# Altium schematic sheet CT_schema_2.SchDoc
size 349 x 342 mm
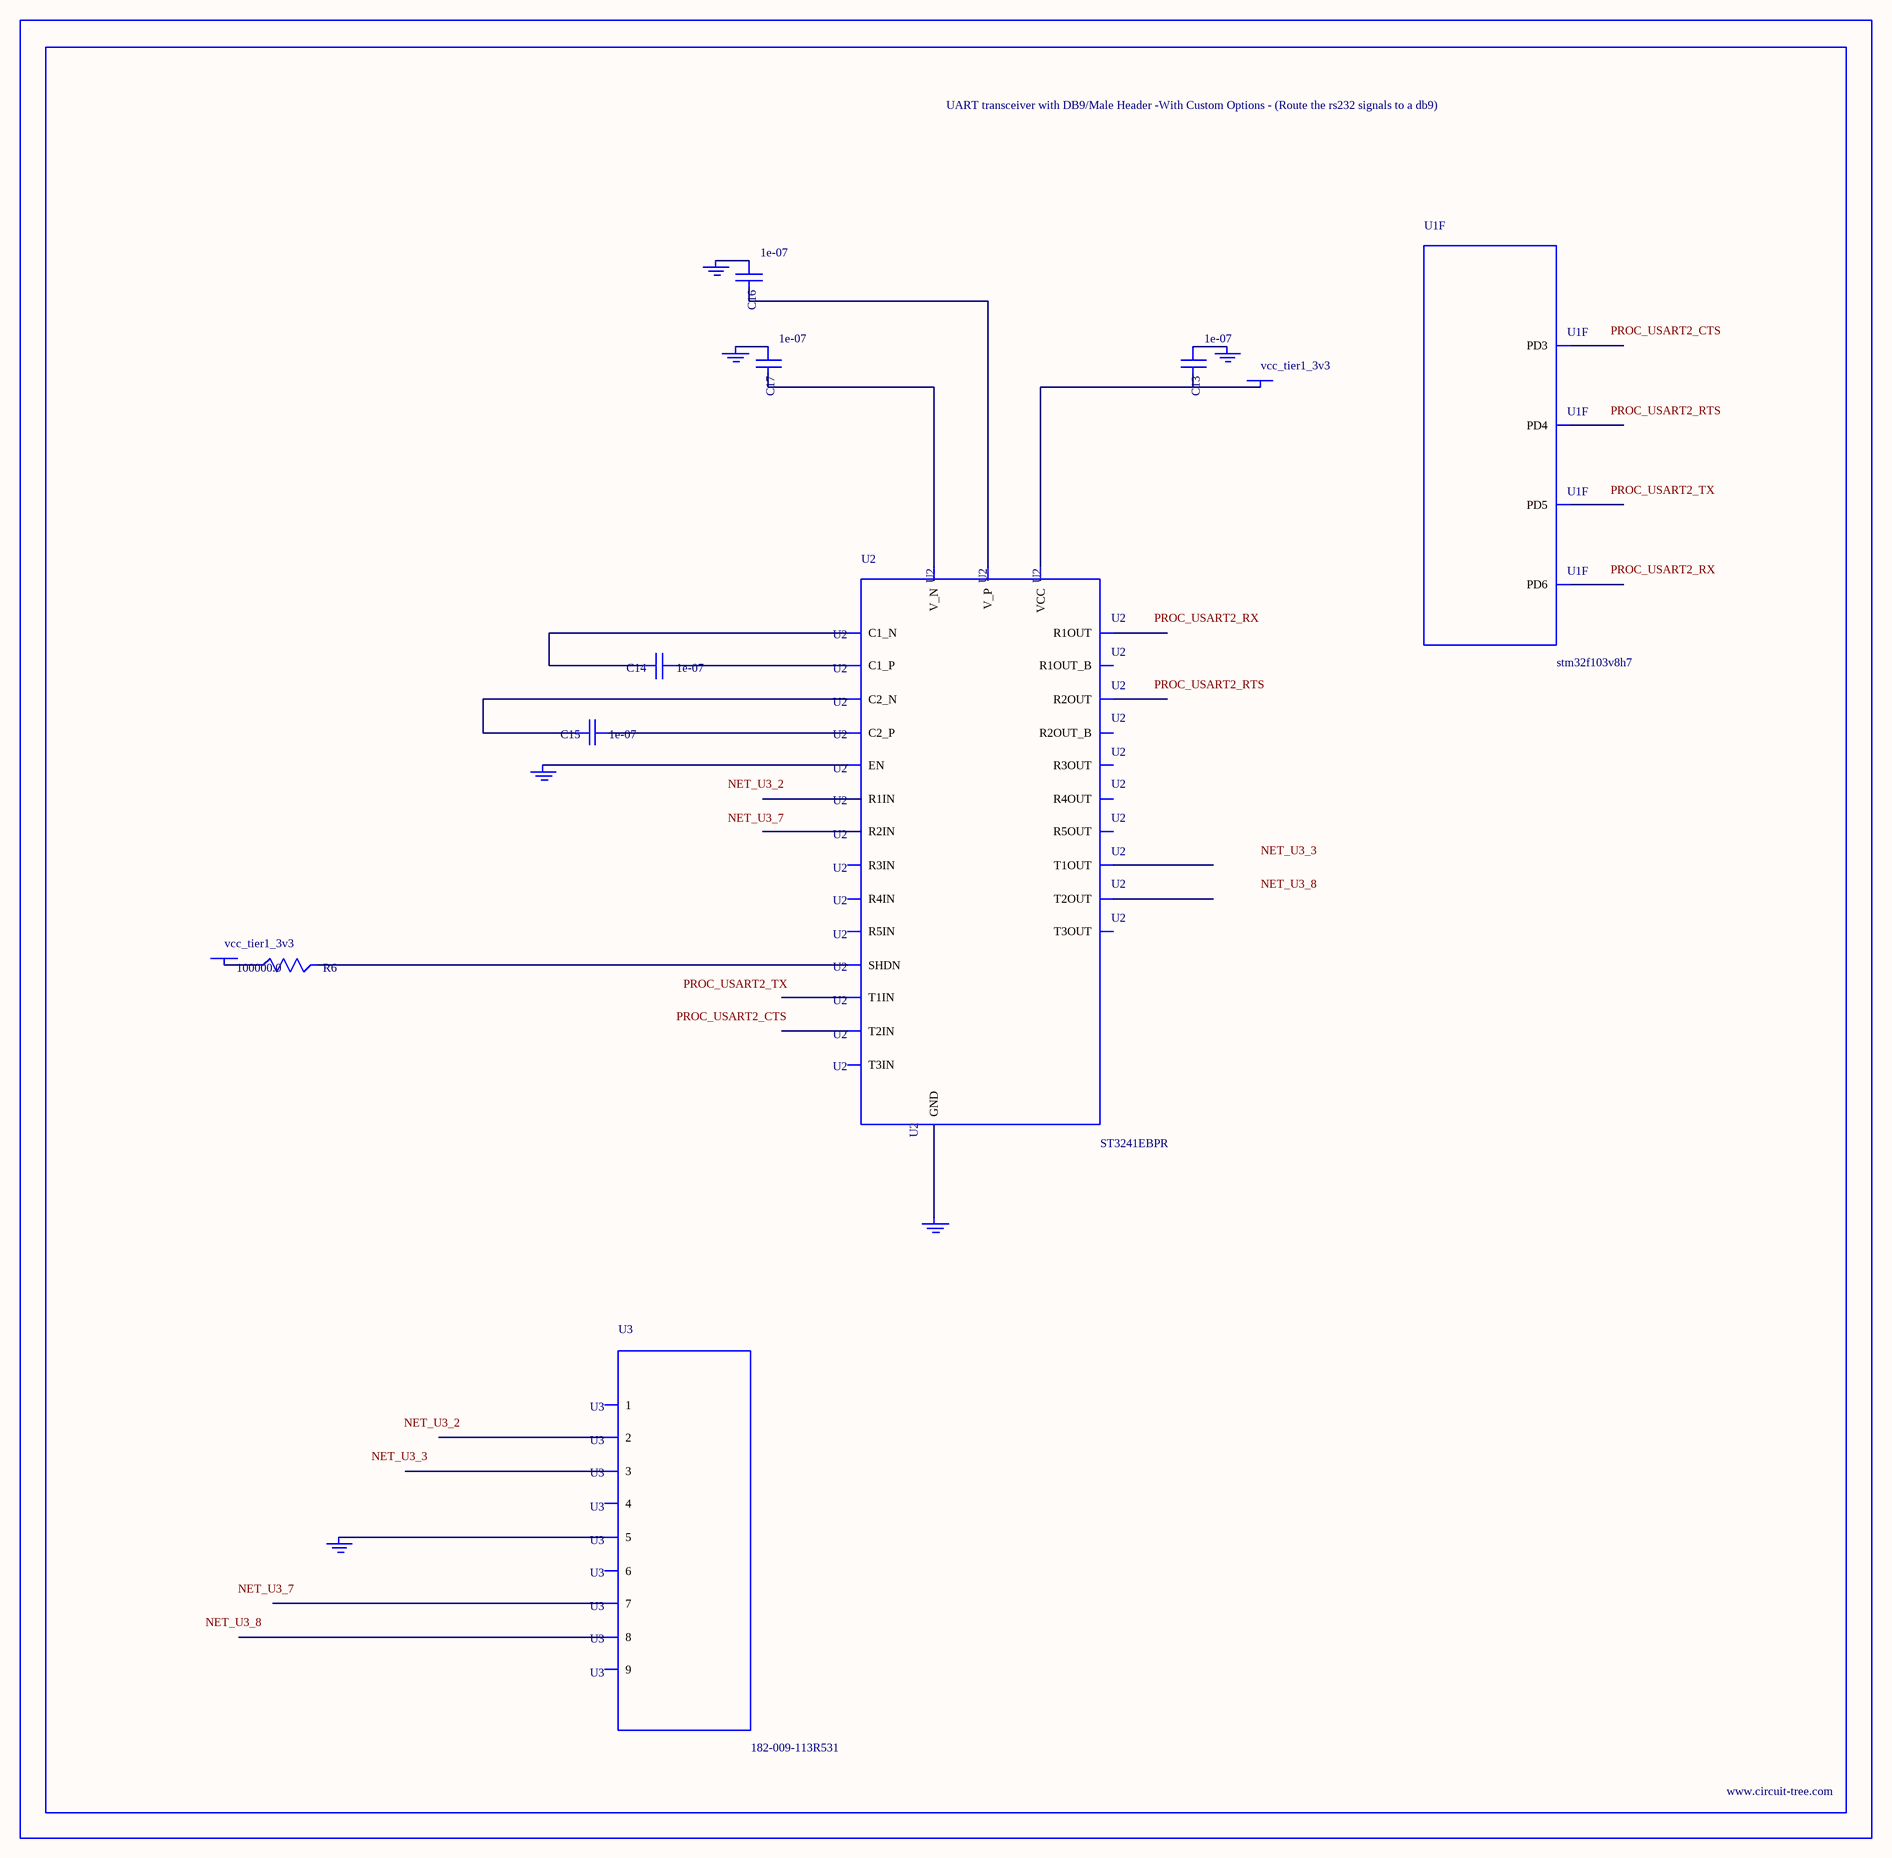
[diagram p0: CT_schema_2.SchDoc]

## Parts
BORDER1  (no value)
C13  1e-07  [C0402]
C14  1e-07  [C0402]
C15  1e-07  [C0402]
C16  1e-07  [C0402]
C17  1e-07  [C0402]
GND_INSTANCE_1_0  (no value)
GND_INSTANCE_1_1  (no value)
GND_INSTANCE_1_2  (no value)
GND_INSTANCE_1_3  (no value)
GND_INSTANCE_1_4  (no value)
GND_INSTANCE_1_5  (no value)
POWER_INSTANCE_1_0  vcc_tier1_3v3
POWER_INSTANCE_1_1  vcc_tier1_3v3
R6  100000.0  [R0603]
U1  stm32f103v8h7  [LFBGA100]  (part F of 9)
U2  ST3241EBPR  [SSOP-28]
U3  182-009-113R531  [182-009-MALE]

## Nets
NetC13_1: C13.1 GND_INSTANCE_1_2.0(GND)
NetC13_2: C13.2 POWER_INSTANCE_1_1.0(PWR) U2.26(VCC)
NetC14_1: C14.1 U2.28(C1_P)
NetC14_2: C14.2 U2.24(C1_N)
NetC15_1: C15.1 U2.1(C2_P)
NetC15_2: C15.2 U2.2(C2_N)
NetC16_1: C16.1 GND_INSTANCE_1_3.0(GND)
NetC16_2: C16.2 U2.27(V_P)
NetC17_1: C17.1 GND_INSTANCE_1_0.0(GND)
NetC17_2: C17.2 U2.3(V_N)
NetGND_INSTANCE_1_1_0: GND_INSTANCE_1_1.0(GND) U2.23(EN)
NetGND_INSTANCE_1_4_0: GND_INSTANCE_1_4.0(GND) U2.25(GND)
NetGND_INSTANCE_1_5_0: GND_INSTANCE_1_5.0(GND) U3.5
NetPOWER_INSTANCE_1_0_0: POWER_INSTANCE_1_0.0(PWR) R6.1
NetR6_2: R6.2 U2.22(SHDN)

Not connected (* = marked no-connect by the designer): U1 B6(PD5) C6(PD6) C7(PD3) D7(PD4); U2 4(R1IN) 5(R2IN) 6(R3IN) 7(R4IN) 8(R5IN) 9(T1OUT) 10(T2OUT) 11(T3OUT) 12(T3IN) 13(T2IN) 14(T1IN) 15(R5OUT) 16(R4OUT) 17(R3OUT) 18(R2OUT) 19(R1OUT) 20(R2OUT_B) 21(R1OUT_B); U3 1 2 3 4 6 7 8 9

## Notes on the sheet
- Labels drawn without touching a wire or pin: NET_U3_2, NET_U3_3, NET_U3_7, NET_U3_8, PROC_USART2_CTS, PROC_USART2_RTS, PROC_USART2_RX, PROC_USART2_TX

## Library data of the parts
BORDER1 = BORDER_PAGE1
C13-C17 = C0402C104K3RACTU
GND_INSTANCE_1_0-GND_INSTANCE_1_5 = GND
POWER_INSTANCE_1_0 POWER_INSTANCE_1_1 = PWR
R6 = RC0603JR-07100KL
